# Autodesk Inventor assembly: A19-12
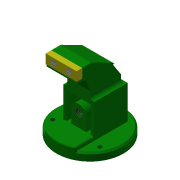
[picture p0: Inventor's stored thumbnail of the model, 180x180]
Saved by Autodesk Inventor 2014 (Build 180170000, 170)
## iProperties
Created: 2008-07
Part Number: A19-12
Document SubType Name: Assembly
Designer: y-shimohigashi
Stock Number: A19-12
Author: y-shimohigashi
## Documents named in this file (4)
- \\SVFL01\Data\技術\CAD\Inventor\テキスト\Inventor_教育Text\R2014（仮）\Inventor2014基礎コース\練習問題-19\A19-12.iam
- \\SVFL01\Data\技術\CAD\Inventor\テキスト\Inventor_教育Text\R2014（仮）\Inventor2014基礎コース\練習問題-19\P19-2ベース.ipt
- \\SVFL01\Data\技術\CAD\Inventor\テキスト\Inventor_教育Text\R2014（仮）\Inventor2014基礎コース\練習問題-19\P19-4締付板.ipt
- \\SVFL01\Data\技術\CAD\Inventor\テキスト\Inventor_教育Text\R2014（仮）\Inventor2014基礎コース\練習問題-19\P19-11ボルト.ipt
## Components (4 placed, 3 different names)
1. P19-2ベース:1
2. P19-4締付板:1 — 挿入:2, 挿入:3
3. P19-11ボルト:1 — 挿入:2
4. P19-11ボルト:2 — 挿入:3
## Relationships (2: Insert 2)
- 挿入:2 [Insert]: P19-4締付板:1 ↔ P19-11ボルト:1
- 挿入:3 [Insert]: P19-4締付板:1 ↔ P19-11ボルト:2
